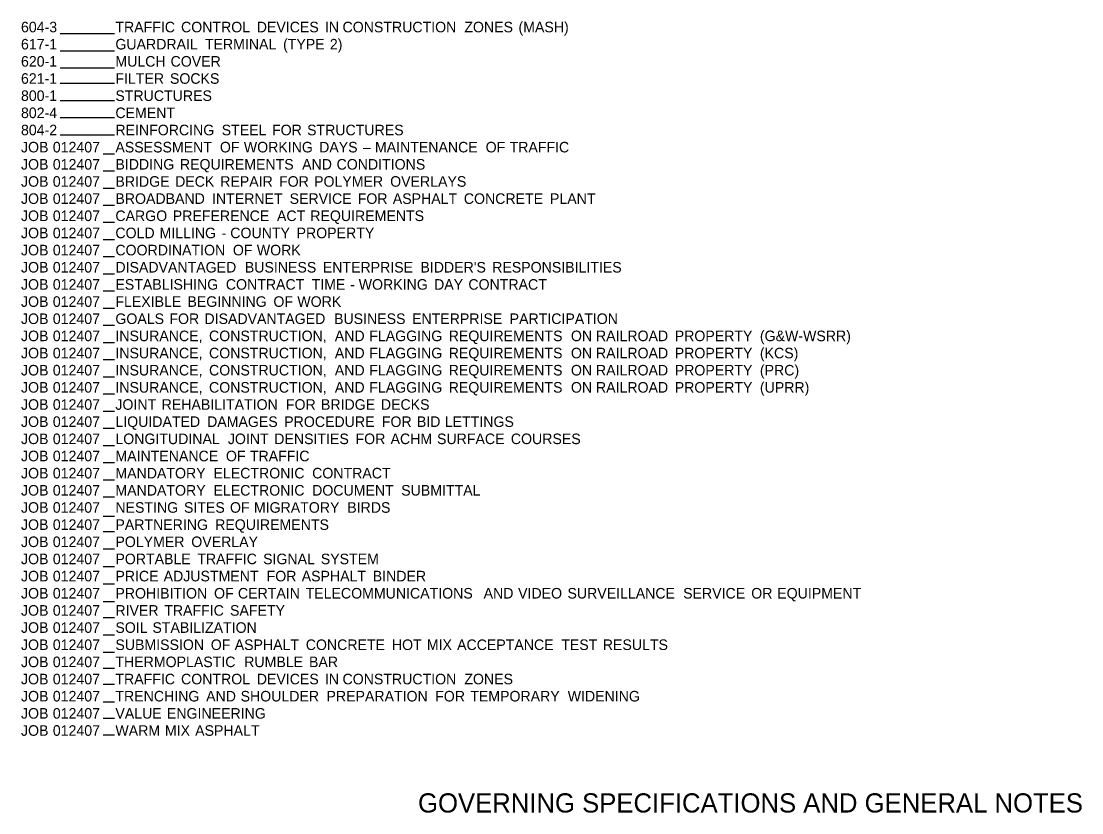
# Model space of a CAD drawing. Extents: x 1930579 to 1932218, y 596452 to 599480.
# Drawn here: x 1931525 to 1932188, y 598494 to 598989 of the extents above; entities that cross this region are included whole.
import ezdxf

# ---------------------------------------------------------------- set-up
doc = ezdxf.new("R2010")
doc.units = 0
doc.layers.add('Default', color=7, linetype='Continuous')
doc.layers.add('R_Border', color=7, linetype='Continuous')

msp = doc.modelspace()

# ---------------------------------------------------------------- linework, layer by layer
at = {"layer": 'R_Border'}
for p, q in [((1931549.9, 598981.34), (1931583.8, 598981.34)), ((1931549.9, 598970.62), (1931583.8, 598970.62)), ((1931549.9, 598959.89), (1931583.8, 598959.89)), ((1931549.9, 598950.33), (1931583.8, 598950.33)), ((1931549.9, 598939.6), (1931583.8, 598939.6)), ((1931549.9, 598928.88), (1931583.8, 598928.88)), ((1931549.9, 598918.15), (1931583.8, 598918.15)), ((1931576.59, 598906.27), (1931583.8, 598906.27)), ((1931576.59, 598895.54), (1931583.8, 598895.54)), ((1931576.59, 598884.82), (1931583.8, 598884.82)), ((1931576.59, 598874.09), (1931583.8, 598874.09)), ((1931576.59, 598863.37), (1931583.8, 598863.37)), ((1931576.59, 598852.64), (1931583.8, 598852.64)), ((1931576.59, 598841.92), (1931583.8, 598841.92)), ((1931576.59, 598831.19), (1931583.8, 598831.19)), ((1931576.59, 598820.47), (1931583.8, 598820.47)), ((1931576.59, 598809.74), (1931583.8, 598809.74)), ((1931576.59, 598799.02), (1931583.8, 598799.02)), ((1931576.59, 598788.29), (1931583.8, 598788.29)), ((1931576.59, 598777.57), (1931583.8, 598777.57)), ((1931576.59, 598766.84), (1931583.8, 598766.84)), ((1931576.59, 598756.12), (1931583.8, 598756.12)), ((1931576.59, 598745.39), (1931583.8, 598745.39)), ((1931576.59, 598734.67), (1931583.8, 598734.67)), ((1931576.59, 598723.94), (1931583.8, 598723.94)), ((1931576.59, 598713.22), (1931583.8, 598713.22)), ((1931576.59, 598702.49), (1931583.8, 598702.49)), ((1931576.59, 598691.77), (1931583.8, 598691.77)), ((1931576.59, 598679.68), (1931583.8, 598679.68)), ((1931576.59, 598670.13), (1931583.8, 598670.13)), ((1931576.59, 598659.2), (1931583.8, 598659.2)), ((1931576.59, 598648.26), (1931583.8, 598648.26)), ((1931576.59, 598637.33), (1931583.8, 598637.33)), ((1931576.59, 598626.4), (1931583.8, 598626.4)), ((1931576.59, 598616.3), (1931583.8, 598616.3)), ((1931576.59, 598605.49), (1931583.8, 598605.49)), ((1931576.59, 598594.67), (1931583.8, 598594.67)), ((1931576.59, 598584.66), (1931583.8, 598584.66)), ((1931576.59, 598574.64), (1931583.8, 598574.64)), ((1931576.59, 598563.63), (1931583.8, 598563.63)), ((1931576.59, 598553.34), (1931583.8, 598553.34)), ((1931576.59, 598543.05), (1931583.8, 598543.05))]:
    msp.add_line(p, q, dxfattribs=at)

# ---------------------------------------------------------------- texts
at = {"layer": 'Default'}
for s, p in [('604-3', (1931525.34, 598982.13)), ('TRAFFIC', (1931584.33, 598982.13)), (' CONTROL', (1931622.9, 598982.13)), (' DEVICES', (1931670.22, 598982.13)), (' IN', (1931712.79, 598982.13)), (' CONSTRUCTION', (1931723.81, 598982.13)), (' ZONES', (1931799.91, 598982.13)), (' (MASH)', (1931833.76, 598982.13)), ('617-1', (1931525.34, 598971.41)), ('GUARDRAIL', (1931584.33, 598971.41)), (' TERMINAL', (1931637.81, 598971.41)), (' (TYPE', (1931686.67, 598971.41)), (' 2)', (1931715.89, 598971.41)), ('620-1', (1931525.34, 598960.68)), ('MULCH', (1931584.33, 598960.68)), (' COVER', (1931616.37, 598960.68)), ('621-1', (1931525.34, 598949.96)), ('FILTER', (1931584.33, 598949.96)), (' SOCKS', (1931615.97, 598949.96)), ('800-1', (1931525.34, 598939.23)), ('STRUCTURES', (1931584.33, 598939.23)), ('802-4', (1931525.34, 598928.51)), ('CEMENT', (1931584.33, 598928.51)), ('804-2', (1931525.34, 598917.78)), ('REINFORCING', (1931584.33, 598917.78)), (' STEEL', (1931648.3, 598917.78)), (' FOR', (1931679.76, 598917.78)), (' STRUCTURES', (1931701.66, 598917.78)), ('JOB', (1931525.34, 598907.06)), (' 012407', (1931542.79, 598907.06)), ('ASSESSMENT', (1931584.33, 598907.06)), (' OF', (1931647.18, 598907.06)), (' WORKING', (1931662.13, 598907.06)), (' DAYS', (1931709.19, 598907.06)), (' MAINTENANCE', (1931744.05, 598907.06)), (' OF', (1931813.25, 598907.06)), (' TRAFFIC', (1931828.19, 598907.06)), ('–', (1931738.95, 598907.06)), ('JOB', (1931525.34, 598896.33)), (' 012407', (1931542.79, 598896.33)), ('BIDDING', (1931584.33, 598896.33)), (' REQUIREMENTS', (1931622.18, 598896.33)), (' AND', (1931698.55, 598896.33)), (' CONDITIONS', (1931720.09, 598896.33)), ('JOB', (1931525.34, 598885.61)), (' 012407', (1931542.79, 598885.61)), ('BRIDGE', (1931584.33, 598885.61)), (' DECK', (1931619.19, 598885.61)), (' REPAIR', (1931647.36, 598885.61)), (' FOR', (1931684.13, 598885.61)), (' POLYMER', (1931706.03, 598885.61)), (' OVERLAYS', (1931753.57, 598885.61)), ('JOB', (1931525.34, 598874.88)), (' 012407', (1931542.79, 598874.88)), ('BROADBAND', (1931584.33, 598874.88)), (' INTERNET', (1931642.26, 598874.88)), (' SERVICE', (1931690.75, 598874.88)), (' FOR', (1931733.3, 598874.88)), (' ASPHALT', (1931755.21, 598874.88)), (' CONCRETE', (1931799.61, 598874.88)), (' PLANT', (1931853.43, 598874.88)), ('JOB', (1931525.34, 598864.16)), (' 012407', (1931542.79, 598864.16)), ('CARGO', (1931584.33, 598864.16)), (' PREFERENCE', (1931617.73, 598864.16)), (' ACT', (1931682.84, 598864.16)), (' REQUIREMENTS', (1931703.66, 598864.16)), ('JOB', (1931525.34, 598853.43)), (' 012407', (1931542.79, 598853.43)), ('COLD', (1931584.33, 598853.43)), (' MILLING', (1931609.45, 598853.43)), (' COUNTY', (1931653.67, 598853.43)), (' PROPERTY', (1931695.1, 598853.43)), (' -', (1931648.32, 598853.43)), ('JOB', (1931525.34, 598842.71)), (' 012407', (1931542.79, 598842.71)), ('COORDINATION', (1931584.33, 598842.71)), (' OF', (1931655.3, 598842.71)), (' WORK', (1931670.25, 598842.71)), ('JOB', (1931525.34, 598831.98)), (' 012407', (1931542.79, 598831.98)), ('DISADVANTAGED', (1931584.33, 598831.98)), (' BUSINESS', (1931662.76, 598831.98)), (' ENTERPRISE', (1931711.48, 598831.98)), (" BIDDER'S", (1931772.48, 598831.98)), (' RESPONSIBILITIES', (1931817.32, 598831.98)), ('JOB', (1931525.34, 598821.26)), (' 012407', (1931542.79, 598821.26)), ('ESTABLISHING', (1931584.33, 598821.26)), (' CONTRACT', (1931650.89, 598821.26)), (' TIME', (1931704.5, 598821.26)), (' WORKING', (1931733.93, 598821.26)), (' DAY', (1931781, 598821.26)), (' CONTRACT', (1931802.45, 598821.26)), (' -', (1931728.59, 598821.26)), ('JOB', (1931525.34, 598810.53)), (' 012407', (1931542.79, 598810.53)), ('FLEXIBLE', (1931584.33, 598810.53)), (' BEGINNING', (1931626.89, 598810.53)), (' OF', (1931680.63, 598810.53)), (' WORK', (1931695.57, 598810.53)), ('JOB', (1931525.34, 598799.81)), (' 012407', (1931542.79, 598799.81)), ('GOALS', (1931584.33, 598799.81)), (' FOR', (1931615.62, 598799.81)), (' DISADVANTAGED', (1931637.52, 598799.81)), (' BUSINESS', (1931718.52, 598799.81)), (' ENTERPRISE', (1931767.24, 598799.81)), (' PARTICIPATION', (1931828.24, 598799.81)), ('JOB', (1931525.34, 598789.08)), (' 012407', (1931542.79, 598789.08)), ('INSURANCE,', (1931584.33, 598789.08)), (' CONSTRUCTION,', (1931640.39, 598789.08)), (' AND', (1931718.98, 598789.08)), (' FLAGGING', (1931740.52, 598789.08)), (' REQUIREMENTS', (1931790.15, 598789.08)), (' ON', (1931866.53, 598789.08)), (' RAILROAD', (1931882.17, 598789.08)), (' PROPERTY', (1931931.39, 598789.08)), (' (G&W-WSRR)', (1931984.61, 598789.08)), ('JOB', (1931525.34, 598778.36)), (' 012407', (1931542.79, 598778.36)), ('INSURANCE,', (1931584.33, 598778.36)), (' CONSTRUCTION,', (1931640.39, 598778.36)), (' AND', (1931718.98, 598778.36)), (' FLAGGING', (1931740.52, 598778.36)), (' REQUIREMENTS', (1931790.15, 598778.36)), (' ON', (1931866.53, 598778.36)), (' RAILROAD', (1931882.17, 598778.36)), (' PROPERTY', (1931931.39, 598778.36)), (' (KCS)', (1931984.61, 598778.36)), ('JOB', (1931525.34, 598767.63)), (' 012407', (1931542.79, 598767.63)), ('INSURANCE,', (1931584.33, 598767.63)), (' CONSTRUCTION,', (1931640.39, 598767.63)), (' AND', (1931718.98, 598767.63)), (' FLAGGING', (1931740.52, 598767.63)), (' REQUIREMENTS', (1931790.15, 598767.63)), (' ON', (1931866.53, 598767.63)), (' RAILROAD', (1931882.17, 598767.63)), (' PROPERTY', (1931931.39, 598767.63)), (' (PRC)', (1931984.61, 598767.63)), ('JOB', (1931525.34, 598756.91)), (' 012407', (1931542.79, 598756.91)), ('INSURANCE,', (1931584.33, 598756.91)), (' CONSTRUCTION,', (1931640.39, 598756.91)), (' AND', (1931718.98, 598756.91)), (' FLAGGING', (1931740.52, 598756.91)), (' REQUIREMENTS', (1931790.15, 598756.91)), (' ON', (1931866.53, 598756.91)), (' RAILROAD', (1931882.17, 598756.91)), (' PROPERTY', (1931931.39, 598756.91)), (' (UPRR)', (1931984.61, 598756.91)), ('JOB', (1931525.34, 598746.18)), (' 012407', (1931542.79, 598746.18)), ('JOINT', (1931584.33, 598746.18)), (' REHABILITATION', (1931610.78, 598746.18)), (' FOR', (1931688.43, 598746.18)), (' BRIDGE', (1931710.33, 598746.18)), (' DECKS', (1931747.76, 598746.18)), ('JOB', (1931525.34, 598735.46)), (' 012407', (1931542.79, 598735.46)), ('LIQUIDATED', (1931584.33, 598735.46)), (' DAMAGES', (1931639.17, 598735.46)), (' PROCEDURE', (1931687.38, 598735.46)), (' FOR', (1931748.38, 598735.46)), (' BID', (1931770.28, 598735.46)), (' LETTINGS', (1931787.72, 598735.46)), ('JOB', (1931525.34, 598724.73)), (' 012407', (1931542.79, 598724.73)), ('LONGITUDINAL', (1931584.33, 598724.73)), (' JOINT', (1931652.15, 598724.73)), (' DENSITIES', (1931681.16, 598724.73)), (' FOR', (1931731.93, 598724.73)), (' ACHM', (1931753.83, 598724.73)), (' SURFACE', (1931782.85, 598724.73)), (' COURSES', (1931828.99, 598724.73)), ('JOB', (1931525.34, 598714.01)), (' 012407', (1931542.79, 598714.01)), ('MAINTENANCE', (1931584.33, 598714.01)), (' OF', (1931650.96, 598714.01)), (' TRAFFIC', (1931665.91, 598714.01)), ('JOB', (1931525.34, 598703.28)), (' 012407', (1931542.79, 598703.28)), ('MANDATORY', (1931584.33, 598703.28)), (' ELECTRONIC', (1931643.18, 598703.28)), (' CONTRACT', (1931704.82, 598703.28)), ('JOB', (1931525.34, 598692.56)), (' 012407', (1931542.79, 598692.56)), ('MANDATORY', (1931584.33, 598692.56)), (' ELECTRONIC', (1931643.18, 598692.56)), (' DOCUMENT', (1931704.82, 598692.56)), (' SUBMITTAL', (1931760.47, 598692.56)), ('JOB', (1931525.34, 598681.83)), (' 012407', (1931542.79, 598681.83)), ('NESTING', (1931584.33, 598681.83)), (' SITES', (1931624.74, 598681.83)), (' OF', (1931653.47, 598681.83)), (' MIGRATORY', (1931668.42, 598681.83)), (' BIRDS', (1931726.76, 598681.83)), ('JOB', (1931525.34, 598671.11)), (' 012407', (1931542.79, 598671.11)), ('PARTNERING', (1931584.33, 598671.11)), (' REQUIREMENTS', (1931644.21, 598671.11)), ('JOB', (1931525.34, 598660.38)), (' 012407', (1931542.79, 598660.38)), ('POLYMER', (1931584.33, 598660.38)), (' OVERLAY', (1931629.3, 598660.38)), ('JOB', (1931525.34, 598649.66)), (' 012407', (1931542.79, 598649.66)), ('PORTABLE', (1931584.33, 598649.66)), (' TRAFFIC', (1931633.04, 598649.66)), (' SIGNAL', (1931674.17, 598649.66)), (' SYSTEM', (1931710.22, 598649.66)), ('JOB', (1931525.34, 598638.93)), (' 012407', (1931542.79, 598638.93)), ('PRICE', (1931584.33, 598638.93)), (' ADJUSTMENT', (1931612.02, 598638.93)), (' FOR', (1931676.39, 598638.93)), (' ASPHALT', (1931698.3, 598638.93)), (' BINDER', (1931742.7, 598638.93)), ('JOB', (1931525.34, 598628.21)), (' 012407', (1931542.79, 598628.21)), ('PROHIBITION', (1931584.33, 598628.21)), (' OF', (1931643.52, 598628.21)), (' CERTAIN', (1931658.47, 598628.21)), (' TELECOMMUNICATIONS', (1931700.75, 598628.21)), (' AND', (1931811.97, 598628.21)), (' VIDEO', (1931833.51, 598628.21)), (' SURVEILLANCE', (1931864.35, 598628.21)), (' SERVICE', (1931936.64, 598628.21)), (' OR', (1931979.19, 598628.21)), (' EQUIPMENT', (1931995.46, 598628.21)), ('JOB', (1931525.34, 598617.48)), (' 012407', (1931542.79, 598617.48)), ('RIVER', (1931584.33, 598617.48)), (' TRAFFIC', (1931612.39, 598617.48)), (' SAFETY', (1931653.52, 598617.48)), ('JOB', (1931525.34, 598606.76)), (' 012407', (1931542.79, 598606.76)), ('SOIL', (1931584.33, 598606.76)), (' STABILIZATION', (1931605.01, 598606.76)), ('JOB', (1931525.34, 598596.03)), (' 012407', (1931542.79, 598596.03)), ('SUBMISSION', (1931584.33, 598596.03)), (' OF', (1931641.48, 598596.03)), (' ASPHALT', (1931656.42, 598596.03)), (' CONCRETE', (1931700.83, 598596.03)), (' HOT', (1931754.65, 598596.03)), (' MIX', (1931776.49, 598596.03)), (' ACCEPTANCE', (1931795.39, 598596.03)), (' TEST', (1931860.49, 598596.03)), (' RESULTS', (1931886.44, 598596.03)), ('JOB', (1931525.34, 598585.31)), (' 012407', (1931542.79, 598585.31)), ('THERMOPLASTIC', (1931584.33, 598585.31)), (' RUMBLE', (1931662.36, 598585.31)), (' BAR', (1931702.86, 598585.31)), ('JOB', (1931525.34, 598574.58)), (' 012407', (1931542.79, 598574.58)), ('TRAFFIC', (1931584.33, 598574.58)), (' CONTROL', (1931622.9, 598574.58)), (' DEVICES', (1931670.22, 598574.58)), (' IN', (1931712.79, 598574.58)), (' CONSTRUCTION', (1931723.81, 598574.58)), (' ZONES', (1931799.91, 598574.58)), ('JOB', (1931525.34, 598563.86)), (' 012407', (1931542.79, 598563.86)), ('TRENCHING', (1931584.33, 598563.86)), (' AND', (1931638.57, 598563.86)), (' SHOULDER', (1931660.11, 598563.86)), (' PREPARATION', (1931713.79, 598563.86)), (' FOR', (1931781.71, 598563.86)), (' TEMPORARY', (1931803.61, 598563.86)), (' WIDENING', (1931864.52, 598563.86)), ('JOB', (1931525.34, 598553.13)), (' 012407', (1931542.79, 598553.13)), ('VALUE', (1931584.33, 598553.13)), (' ENGINEERING', (1931614.08, 598553.13)), ('JOB', (1931525.34, 598542.41)), (' 012407', (1931542.79, 598542.41)), ('WARM', (1931584.33, 598542.41)), (' MIX', (1931612.83, 598542.41)), (' ASPHALT', (1931631.72, 598542.41))]:
    msp.add_text(s, height=6.6, dxfattribs=at).set_placement(p)
at = {"layer": 'R_Border'}
msp.add_text('GOVERNING SPECIFICATIONS AND GENERAL NOTES ', height=12, rotation=360, dxfattribs=at).set_placement((1931773.43, 598494.45))

doc.saveas('drawing.dxf')
